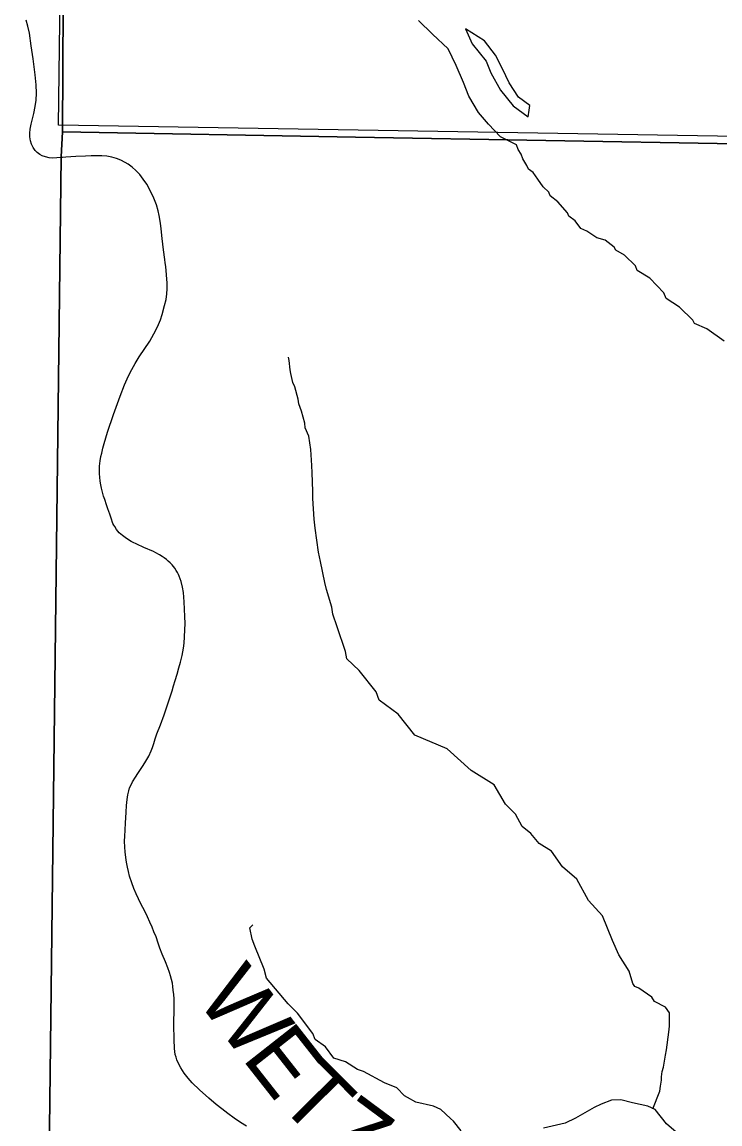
# Model space of a CAD drawing. Extents: x 0 to 34, y -8.9 to 22.
# Drawn here: x 26.101 to 26.715, y 16.454 to 17.424 of the extents above; entities that cross this region are included whole.
import ezdxf

# ---------------------------------------------------------------- set-up
doc = ezdxf.new("R2010")
doc.units = 0
for name, color, linetype in [('GM_X_Corporation', 7, 'Continuous'), ('GM_X_Minor_Lake', 7, 'Continuous'), ('GM_X_Minor_River', 7, 'Continuous'), ('GM_X_Township_Road', 7, 'Continuous'), ('GM_X_Township_Road_Text', 7, 'Continuous')]:
    doc.layers.add(name, color=color, linetype=linetype)

msp = doc.modelspace()

# ---------------------------------------------------------------- linework, layer by layer
at = {"layer": 'GM_X_Corporation'}
for points in [[(23.71667, 19.34001), (23.71667, 15.99131), (24.06511, 15.98282), (24.27706, 15.98069), (24.82679, 15.96404), (25.67852, 15.94183), (25.79223, 15.93902), (26.11864, 15.93664), (26.13505, 17.30548), (26.13606, 17.32776), (26.13906, 17.88469), (26.13986, 18.30373), (25.73809, 18.31201), (25.20826, 18.31084), (25.10455, 18.31168), (25.11243, 18.59321), (25.12162, 18.61936), (25.125, 18.63541), (25.12289, 18.69663), (25.1136, 18.8385), (25.10675, 18.86752), (25.10661, 19.32319), (25.05043, 19.32366), (24.51809, 19.32954)], [(26.14535, 18.31046), (27.19802, 18.31403), (27.16997, 17.31605), (26.13263, 17.33341)], [(23.71667, 15.99131), (23.71667, 14.6), (28.17389, 14.6), (28.1809, 15.29867), (28.19184, 16.15092), (28.18456, 16.33414), (28.1817, 16.6637), (28.19281, 16.80535), (28.18821, 17.31083), (27.91098, 17.31044), (27.47976, 17.3159), (27.05609, 17.31174), (26.72923, 17.31694), (26.39404, 17.3229), (26.13606, 17.32776), (26.13505, 17.30548), (26.11864, 15.93664), (25.79223, 15.93902), (25.67852, 15.94183), (24.82679, 15.96404), (24.27706, 15.98069), (24.06511, 15.98282)]]:
    msp.add_lwpolyline(points, close=True, dxfattribs=at)
for points in [[(26.13906, 17.88469), (26.13606, 17.32776), (26.39404, 17.3229), (26.72923, 17.31694), (27.05609, 17.31174), (27.47976, 17.3159), (27.91098, 17.31044), (28.18821, 17.31083), (28.201, 18.0921)], [(29.55275, 16.78351), (28.31818, 16.80017), (28.19281, 16.80535), (28.18821, 17.31083), (27.91098, 17.31044), (27.47976, 17.3159), (27.05609, 17.31174), (26.72923, 17.31694), (26.39404, 17.3229), (26.13606, 17.32776), (26.13906, 17.88469)], [(26.13906, 17.88469), (26.13606, 17.32776), (26.39404, 17.3229), (26.72923, 17.31694), (27.05609, 17.31174), (27.47976, 17.3159), (27.91098, 17.31044), (28.18821, 17.31083), (28.19281, 16.80535), (28.31818, 16.80017), (29.55275, 16.78351)]]:
    msp.add_lwpolyline(points, dxfattribs=at)
at = {"layer": 'GM_X_Minor_Lake'}
for points in [[(26.49099, 17.41848), (26.49682, 17.40527), (26.50913, 17.38985), (26.51342, 17.37966), (26.52193, 17.3642), (26.53308, 17.35066), (26.54608, 17.34094), (26.54689, 17.34664)], [(26.54689, 17.34664), (26.54748, 17.35082), (26.53754, 17.3583), (26.52944, 17.37073), (26.52361, 17.38318), (26.51741, 17.39525), (26.50779, 17.40767), (26.49099, 17.41848)]]:
    msp.add_lwpolyline(points, dxfattribs=at)
at = {"layer": 'GM_X_Minor_River'}
for points in [[(26.52168, 17.32328), (26.51128, 17.33449), (26.50244, 17.34463), (26.49394, 17.35896), (26.48925, 17.37105), (26.48264, 17.38615), (26.47564, 17.40087), (26.46185, 17.41361), (26.44958, 17.42562)], [(26.53579, 17.31632), (26.52168, 17.32328)], [(26.71873, 17.14331), (26.70336, 17.15409), (26.69265, 17.15886), (26.69107, 17.16187), (26.67949, 17.17309), (26.66759, 17.18088), (26.66561, 17.18578), (26.65323, 17.19888), (26.64211, 17.20555), (26.64052, 17.2097), (26.63086, 17.21905), (26.62319, 17.22349), (26.62201, 17.22613), (26.61393, 17.23208), (26.60668, 17.23424), (26.59785, 17.24018), (26.5925, 17.24238), (26.58745, 17.24913), (26.58206, 17.25323), (26.58087, 17.25625), (26.57235, 17.26599), (26.56542, 17.2712), (26.56423, 17.2746), (26.55921, 17.27908), (26.55454, 17.28585), (26.55064, 17.29186), (26.54642, 17.29484), (26.54484, 17.29785), (26.54132, 17.30387), (26.54011, 17.30803), (26.53738, 17.31217), (26.53579, 17.31632)], [(26.65601, 16.46735), (26.66222, 16.48288), (26.66253, 16.48707), (26.66357, 16.4924), (26.66352, 16.49544), (26.6642, 16.50001), (26.66527, 16.50383), (26.66699, 16.51449), (26.66805, 16.51907), (26.67005, 16.53468), (26.67072, 16.54001), (26.67052, 16.55178), (26.66702, 16.55666), (26.65743, 16.56183), (26.65509, 16.56559), (26.64357, 16.57339), (26.64013, 16.57486), (26.63818, 16.57749), (26.63496, 16.58845), (26.62598, 16.60275), (26.62044, 16.61558), (26.61171, 16.6371), (26.59933, 16.65058), (26.58914, 16.66941), (26.57642, 16.68023), (26.56669, 16.69413), (26.55595, 16.7008), (26.54858, 16.7098), (26.54088, 16.71576), (26.535, 16.72669), (26.52611, 16.73566), (26.51633, 16.75261), (26.49599, 16.7652), (26.47478, 16.78424), (26.44648, 16.79633), (26.43174, 16.81472), (26.41482, 16.82699), (26.41241, 16.83455), (26.39728, 16.85331), (26.38648, 16.86339), (26.38523, 16.86983), (26.37802, 16.89175), (26.37403, 16.90271), (26.37316, 16.90915), (26.36871, 16.92466), (26.36709, 16.93071), (26.36335, 16.94927), (26.36169, 16.9576), (26.35867, 16.97845), (26.35778, 16.98641), (26.3567, 17.00463), (26.35659, 17.01109), (26.35592, 17.02741), (26.35581, 17.03387), (26.35481, 17.04791), (26.35309, 17.05966), (26.34993, 17.06683), (26.34948, 17.071), (26.34664, 17.08159), (26.34425, 17.08802), (26.34379, 17.09219), (26.34057, 17.10316), (26.33898, 17.10693), (26.33733, 17.11488), (26.33652, 17.11791), (26.33561, 17.12625), (26.33518, 17.12928)], [(26.48706, 16.44783), (26.48046, 16.45646), (26.47776, 16.4587), (26.46928, 16.46654), (26.46277, 16.46948), (26.44714, 16.47303), (26.43986, 16.4771), (26.43718, 16.47857), (26.4306, 16.48569), (26.41952, 16.49007), (26.40112, 16.50004), (26.39578, 16.50185), (26.38541, 16.50853), (26.37511, 16.51179), (26.36772, 16.52193), (26.3585, 16.52824), (26.35651, 16.53353), (26.34291, 16.55155), (26.33479, 16.55978), (26.3158, 16.58228), (26.31377, 16.59022), (26.30544, 16.61061), (26.30306, 16.61665), (26.30099, 16.62649), (26.3036, 16.6292)], [(26.67844, 16.44477), (26.66803, 16.4541), (26.65795, 16.46648), (26.65144, 16.46942), (26.6381, 16.47263), (26.62781, 16.47512), (26.61946, 16.47499), (26.61041, 16.47143), (26.60439, 16.46829), (26.58785, 16.45891), (26.57881, 16.45459), (26.55953, 16.45011)]]:
    msp.add_lwpolyline(points, dxfattribs=at)
at = {"layer": 'GM_X_Township_Road'}
for points in [[(26.13624, 17.30503), (26.13525, 17.30495), (26.13116, 17.30462), (26.12743, 17.30457), (26.12434, 17.30487), (26.12131, 17.30551), (26.11838, 17.30655), (26.11617, 17.30768), (26.1137, 17.30953), (26.11199, 17.31133), (26.11023, 17.31387), (26.10887, 17.31665), (26.10797, 17.31961), (26.10736, 17.32327), (26.10725, 17.32635), (26.1076, 17.33005), (26.10852, 17.33429), (26.11103, 17.34389), (26.11222, 17.34997), (26.11288, 17.3555), (26.11317, 17.36167), (26.11298, 17.36909), (26.11221, 17.3777), (26.11045, 17.39181), (26.1087, 17.40347), (26.10695, 17.4145), (26.10564, 17.42057), (26.10408, 17.42594)], [(26.29826, 16.45201), (26.29299, 16.45527), (26.2873, 16.45901), (26.28177, 16.463), (26.27637, 16.46714), (26.27157, 16.47106), (26.26493, 16.4766), (26.25664, 16.48402), (26.25045, 16.49011), (26.24675, 16.49428), (26.24335, 16.4987), (26.24031, 16.5034), (26.23805, 16.50782), (26.23689, 16.51035), (26.23615, 16.51265), (26.23549, 16.51495), (26.235, 16.51767), (26.23467, 16.52037), (26.23433, 16.52829), (26.23421, 16.54128), (26.23454, 16.55615), (26.23438, 16.56422), (26.23409, 16.56805), (26.23373, 16.57164), (26.23335, 16.57487), (26.23286, 16.57792), (26.2322, 16.58113), (26.23131, 16.58444), (26.23043, 16.58741), (26.22893, 16.59148), (26.22676, 16.59663), (26.22389, 16.60348), (26.22192, 16.60868), (26.22044, 16.61302), (26.21854, 16.61863), (26.2167, 16.62323), (26.21518, 16.62716), (26.21306, 16.63174), (26.21102, 16.63625), (26.20884, 16.64069), (26.20694, 16.64459), (26.20461, 16.64894), (26.20304, 16.6523), (26.20087, 16.6567), (26.19896, 16.66124), (26.19721, 16.66615), (26.19524, 16.67216), (26.19417, 16.6761), (26.19332, 16.68005), (26.19244, 16.6844), (26.19194, 16.68846), (26.19137, 16.69344), (26.19107, 16.69755), (26.19088, 16.7029), (26.19098, 16.70733), (26.19121, 16.7126), (26.1916, 16.71901), (26.19179, 16.72353), (26.19212, 16.72855), (26.19263, 16.73445), (26.19318, 16.73956), (26.19378, 16.74366), (26.1945, 16.74721), (26.19524, 16.74983), (26.19647, 16.75255), (26.19787, 16.75518), (26.20044, 16.75942), (26.20242, 16.76258), (26.20485, 16.76611), (26.20722, 16.76971), (26.20962, 16.77335), (26.21209, 16.77778), (26.21431, 16.78239), (26.21546, 16.78543), (26.21653, 16.78888), (26.21784, 16.79299), (26.21931, 16.7974), (26.22241, 16.8055), (26.22559, 16.81424), (26.22679, 16.81776), (26.22861, 16.82307), (26.23029, 16.82831), (26.23264, 16.83537), (26.23395, 16.8396), (26.23535, 16.84429), (26.23716, 16.84987), (26.23872, 16.85563), (26.24012, 16.86048), (26.24152, 16.86656), (26.24264, 16.87292), (26.24332, 16.87741), (26.24368, 16.88279), (26.24398, 16.88898), (26.24404, 16.89457), (26.244, 16.90078), (26.24339, 16.91381), (26.24268, 16.92183), (26.24184, 16.92672), (26.24058, 16.93152), (26.23987, 16.93388), (26.23893, 16.93621), (26.23823, 16.93775), (26.23736, 16.93958), (26.23626, 16.94137), (26.23505, 16.94326), (26.23272, 16.94616), (26.231, 16.94795), (26.22916, 16.94962), (26.22763, 16.95098), (26.22577, 16.95233), (26.22376, 16.95378), (26.22165, 16.95507), (26.21839, 16.95685), (26.21616, 16.95791), (26.21286, 16.95952), (26.21117, 16.96024), (26.20776, 16.96163), (26.20663, 16.96209), (26.2027, 16.9638), (26.19665, 16.96684), (26.1924, 16.96941), (26.18891, 16.972), (26.18618, 16.97454), (26.18496, 16.97581), (26.18378, 16.97738), (26.18211, 16.97998), (26.18134, 16.98132), (26.1806, 16.9828), (26.17889, 16.98737), (26.17768, 16.99089), (26.17603, 16.99555), (26.17481, 16.99903), (26.17328, 17.00373), (26.17234, 17.00665), (26.17142, 17.01024), (26.17042, 17.01377), (26.16983, 17.01674), (26.16934, 17.02004), (26.16901, 17.02365), (26.16885, 17.02653), (26.16875, 17.02946), (26.16878, 17.0331), (26.16934, 17.03801), (26.17003, 17.04168), (26.17071, 17.04471), (26.17174, 17.04892), (26.17289, 17.05311), (26.17586, 17.06325), (26.18093, 17.07858), (26.18683, 17.09494), (26.19076, 17.10474), (26.19431, 17.11268), (26.19709, 17.11822), (26.20013, 17.12363), (26.20374, 17.1294), (26.21291, 17.14335), (26.2167, 17.14975), (26.21975, 17.15586), (26.22233, 17.16218), (26.22392, 17.16688), (26.22606, 17.17467), (26.22728, 17.18011), (26.22799, 17.18502), (26.22827, 17.18934), (26.22822, 17.19431), (26.22773, 17.20174), (26.22701, 17.20911), (26.22663, 17.21215), (26.22627, 17.21521), (26.22509, 17.22379), (26.22382, 17.23361), (26.22292, 17.24222), (26.22233, 17.24712), (26.2213, 17.25381), (26.22043, 17.25811), (26.2188, 17.26346), (26.21658, 17.26926), (26.21365, 17.27543), (26.21031, 17.2814), (26.20724, 17.28607), (26.20418, 17.28998), (26.2008, 17.29363), (26.19756, 17.29653), (26.19406, 17.29909), (26.19141, 17.3007), (26.18752, 17.30262), (26.18373, 17.30413), (26.17945, 17.30536), (26.17518, 17.3061), (26.17082, 17.30659), (26.16639, 17.30658), (26.16146, 17.30655), (26.15651, 17.30624), (26.14786, 17.30582), (26.1392, 17.30526), (26.13624, 17.30503)]]:
    msp.add_lwpolyline(points, dxfattribs=at)

# ---------------------------------------------------------------- texts
at = {"layer": 'GM_X_Township_Road_Text'}
for s, rotation, p in [('W', 307.53115, (26.25282, 16.56459)), ('E', 308.17907, (26.29335, 16.51184)), ('T', 314.73501, (26.32424, 16.4732)), ('Z', 323.38703, (26.3611, 16.43698))]:
    msp.add_text(s, height=0.05682, rotation=rotation, dxfattribs=at).set_placement(p)

doc.saveas('drawing.dxf')
